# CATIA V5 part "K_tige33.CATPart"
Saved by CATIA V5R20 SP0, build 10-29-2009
Part number: tige 33
Publications: "demi largeur tige", "longueur tige", "demi largeur balancier", "epaisseur pieces", "Plan.-55", "liaison 24/33 sur 33", "Droite.1"
Bounding box of the stored display mesh (mm): x -72.5 to 0, y 459.975 to 992.473, z -17.473 to 226.143
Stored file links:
  G:\Khaled_CFAO_2011\SIL\SIL_GR2\mdardier\Khaled\CAD_ThinkMOTION\K_tige33.CATPart
  G:\Khaled_CFAO_2011\SIL\SIL_GR2\mdardier\Khaled\CAD_ThinkMOTION\K_ass_tandem.CATProduct
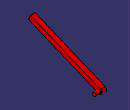
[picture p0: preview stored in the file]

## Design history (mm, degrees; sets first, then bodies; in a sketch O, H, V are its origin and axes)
External parameters (linked from other documents)
  `External.demi largeur tige` = 17.5 mm
  `External.longueur tige` = 550 mm
  `External.demi largeur balancier` = 50 mm
  `External.epaisseur pieces` = 30 mm
Set1
  Plane1 "Plan.-55": linked copy from another document
  Point1 "liaison 24/33 sur 33": linked copy from another document
  Line1: linked copy from another document
Body1 (main body)
  Sketch1 on Plane1, origin (-55, 0, 0), H (0, 1, 0), V (0, 0, 1)
    construction line L1 (466.6562, 209.9681) -> (975, 0)
    point P2 (975, 0)
    line L2 (473.337, 226.1427) -> (981.6808, 16.1746)
    line L3 (968.3192, -16.1746) -> (459.9754, 193.7935)
    arc A1 centre (975, 0) radius 17.5 from (981.6808, 16.1746) to (968.3192, -16.1746) cw
    point P3 (473.337, 226.1427)
    reference projected point E1 (975, 0) from Point1
    reference projected line E2 (466.6562, 209.9681) -> (975, 0) from Line1
    line L4 (473.337, 226.1427) -> (459.9754, 193.7935)
    point P7 (473.337, 226.1427)
    distance L1 L2 = 17.5 {= `External.demi largeur tige`}
    length L2 = 550 {= `External.longueur tige`}
    tangency: A1 L2, A1 L3
    coincidence: P2 E1, P7 L2, P7 P3
    parallelism: L1 E2
    perpendicularity: L4 L1, L4 L2, L4 L3
  Pad1: profile Sketch1, direction (1, 0, 0), length 17.5 {= `External.demi largeur tige`}, mirrored extent
  Sketch2 on end face of Pad1, origin (-37.5, 0, 0), H (0, 1, 0), V (0, 0, 1)
    circle A1 centre (975, 0) radius 12.5
    point P1 (975, 0)
    reference projected point E1 (975, 0) from Point1
    radius A1 = 12.5 {= `External.demi largeur balancier` /4}
    coincidence: P1 E1
  Pad2: profile Sketch2, direction (1, 0, 0), length 37.5 {= `External.demi largeur balancier` /2-`External.demi largeur tige` +`External.epaisseur pieces`}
